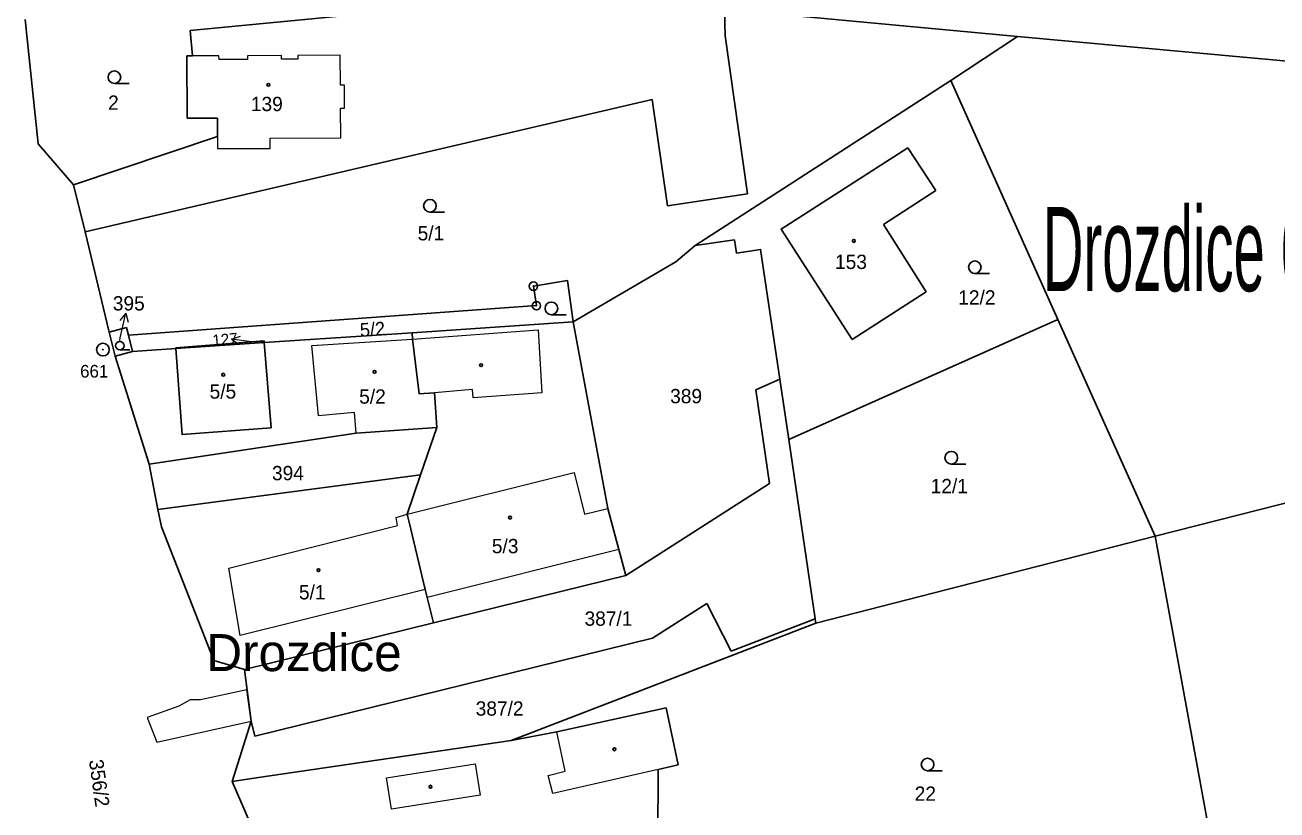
# Model space of a CAD drawing. Extents: x -645290 to -643454, y -1064771 to -1062356.
# Drawn here: x -644572.2 to -644423.3, y -1063667.6 to -1063574.3 of the extents above; entities that cross this region are included whole.
import ezdxf
from ezdxf.enums import TextEntityAlignment as Align

# ---------------------------------------------------------------- set-up
doc = ezdxf.new("R2010")
doc.units = 0
doc.header["$LTSCALE"] = 0.68
for name, color, linetype, lineweight in [('1', 7, 'Continuous', 25), ('13', 7, 'Continuous', 13), ('3', 7, 'Continuous', 25), ('4', 7, 'Continuous', 13), ('5', 7, 'Continuous', 25), ('7', 7, 'Continuous', 13), ('8', 7, 'Continuous', 25)]:
    doc.layers.add(name, color=color, linetype=linetype, lineweight=lineweight)
doc.layers.add('2', color=7, linetype='Continuous')

msp = doc.modelspace()

# ---------------------------------------------------------------- linework, layer by layer
at = {"layer": '1'}
for p, q in [((-644552.52, -1063574.93), (-644514.96, -1063571.32)), ((-644488.95, -1063575.57), (-644489.03, -1063572.44)), ((-644480.96, -1063573.16), (-644454.17, -1063575.65)), ((-644572.16, -1063573.65), (-644570.58, -1063588.42)), ((-644552.26, -1063577.97), (-644552.52, -1063574.93)), ((-644454.17, -1063575.65), (-644462.11, -1063580.89)), ((-644403.42, -1063580.33), (-644454.17, -1063575.65)), ((-644552.91, -1063577.97), (-644552.89, -1063585.38)), ((-644552.26, -1063577.97), (-644552.91, -1063577.97)), ((-644462.11, -1063580.89), (-644492.51, -1063600.51)), ((-644462.11, -1063580.89), (-644449.39, -1063609.28)), ((-644565, -1063598.89), (-644497.63, -1063583.14)), ((-644497.63, -1063583.14), (-644495.79, -1063595.78)), ((-644552.89, -1063585.38), (-644549.27, -1063585.38)), ((-644549.27, -1063585.38), (-644549.27, -1063587.55)), ((-644566.4, -1063593.27), (-644549.27, -1063587.55)), ((-644570.58, -1063588.42), (-644566.4, -1063593.27)), ((-644467.24, -1063588.87), (-644463.91, -1063593.96)), ((-644566.4, -1063593.27), (-644565, -1063598.89)), ((-644463.91, -1063593.96), (-644470.13, -1063598)), ((-644470.13, -1063598), (-644465.06, -1063606.02)), ((-644565, -1063598.89), (-644562.17, -1063610.79)), ((-644492.51, -1063600.51), (-644487.83, -1063599.81)), ((-644487.83, -1063599.81), (-644487.59, -1063601.41)), ((-644494.79, -1063602.46), (-644492.51, -1063600.51)), ((-644506.99, -1063609.57), (-644494.79, -1063602.46)), ((-644507.67, -1063604.66), (-644511.73, -1063605.33)), ((-644507.67, -1063604.66), (-644506.99, -1063609.57)), ((-644511.73, -1063605.33), (-644511.38, -1063607.65)), ((-644465.06, -1063606.02), (-644473.86, -1063611.67)), ((-644511.38, -1063607.65), (-644559.87, -1063611.17)), ((-644562.17, -1063610.79), (-644560.11, -1063610.25)), ((-644560.11, -1063610.25), (-644559.87, -1063611.17)), ((-644526.15, -1063610.87), (-644506.99, -1063609.57)), ((-644502.88, -1063631.75), (-644506.99, -1063609.57)), ((-644481.39, -1063623.58), (-644449.39, -1063609.28)), ((-644449.39, -1063609.28), (-644437.84, -1063635.07)), ((-644562.17, -1063610.79), (-644561.45, -1063613.64)), ((-644559.87, -1063611.17), (-644559.37, -1063613.11)), ((-644526.15, -1063610.87), (-644526.11, -1063611.65)), ((-644526.11, -1063611.65), (-644525.3, -1063618.15)), ((-644561.45, -1063613.64), (-644559.37, -1063613.11)), ((-644561.45, -1063613.64), (-644557.4, -1063626.48)), ((-644485.3, -1063617.66), (-644482.45, -1063616.39)), ((-644482.45, -1063616.39), (-644481.39, -1063623.58)), ((-644525.3, -1063618.15), (-644523.49, -1063618.03)), ((-644523.49, -1063618.03), (-644523.22, -1063622.12)), ((-644483.65, -1063628.81), (-644485.3, -1063617.66)), ((-644532.79, -1063622.8), (-644523.22, -1063622.12)), ((-644523.22, -1063622.12), (-644525.15, -1063627.78)), ((-644557.4, -1063626.48), (-644537.04, -1063623.43)), ((-644537.04, -1063623.43), (-644532.79, -1063622.8)), ((-644481.39, -1063623.58), (-644478.25, -1063644.88)), ((-644557.4, -1063626.48), (-644556.37, -1063631.89)), ((-644556.37, -1063631.89), (-644525.15, -1063627.78)), ((-644525.15, -1063627.78), (-644526.74, -1063632.43)), ((-644500.76, -1063639.72), (-644483.65, -1063628.81)), ((-644420.53, -1063630.64), (-644437.84, -1063635.07)), ((-644556.37, -1063631.89), (-644555.92, -1063633.94)), ((-644526.74, -1063632.43), (-644526.49, -1063633.41)), ((-644502.88, -1063631.75), (-644501.58, -1063636.64)), ((-644555.92, -1063633.94), (-644549.72, -1063649.83)), ((-644526.49, -1063633.41), (-644524.6, -1063641.4)), ((-644478.17, -1063645.39), (-644437.84, -1063635.07)), ((-644437.84, -1063635.07), (-644429.45, -1063680.78)), ((-644501.58, -1063636.64), (-644500.76, -1063639.72)), ((-644523.6, -1063645.36), (-644500.76, -1063639.72)), ((-644524.6, -1063641.4), (-644524.37, -1063642.33)), ((-644524.37, -1063642.33), (-644523.6, -1063645.36)), ((-644497.57, -1063647.18), (-644491.13, -1063643.07)), ((-644491.13, -1063643.07), (-644488.23, -1063648.73)), ((-644488.23, -1063648.73), (-644478.25, -1063644.88)), ((-644478.25, -1063644.88), (-644478.17, -1063645.39)), ((-644546.09, -1063650.91), (-644523.6, -1063645.36)), ((-644514.39, -1063659.34), (-644478.17, -1063645.39)), ((-644544.85, -1063658.85), (-644497.57, -1063647.18)), ((-644549.72, -1063649.83), (-644546.09, -1063650.91)), ((-644546.09, -1063650.91), (-644545.29, -1063657.03)), ((-644508.96, -1063658.32), (-644495.97, -1063655.45)), ((-644495.97, -1063655.45), (-644494.53, -1063662.24)), ((-644545.29, -1063657.03), (-644547.55, -1063664.21)), ((-644545.29, -1063657.03), (-644544.85, -1063658.85)), ((-644544.4, -1063663.73), (-644514.39, -1063659.34)), ((-644514.39, -1063659.34), (-644508.96, -1063658.32)), ((-644494.53, -1063662.24), (-644496.92, -1063662.78)), ((-644547.55, -1063664.21), (-644544.4, -1063663.73)), ((-644547.55, -1063664.21), (-644542.97, -1063674.78)), ((-644496.92, -1063662.78), (-644496.93, -1063678.61))]:
    msp.add_line(p, q, dxfattribs=at)
for points in [[(-644495.79, -1063595.78), (-644486.29, -1063594.35), (-644488.95, -1063575.57)], [(-644473.86, -1063611.67), (-644482.3, -1063598.55), (-644467.24, -1063588.87)], [(-644487.59, -1063601.41), (-644484.73, -1063600.97), (-644482.45, -1063616.39)], [(-644559.37, -1063613.11), (-644554.23, -1063612.76), (-644543.72, -1063612.05)], [(-644543.72, -1063612.05), (-644543.74, -1063611.84), (-644554.24, -1063612.67), (-644554.23, -1063612.76)], [(-644554.23, -1063612.76), (-644553.5, -1063622.98), (-644542.92, -1063622.17), (-644543.72, -1063612.05), (-644526.15, -1063610.87)]]:
    msp.add_lwpolyline(points, dxfattribs=at)
at = {"layer": '13'}
msp.add_lwpolyline([(-644545.29, -1063657.03), (-644545.78, -1063653.31), (-644551.32, -1063654.51), (-644552.53, -1063654.52), (-644553.88, -1063655.28), (-644557.63, -1063656.63), (-644556.51, -1063659.55)], close=True, dxfattribs=at)
at = {"layer": '3'}
for p, q in [((-644561.543, -1063581.24), (-644559.793, -1063581.24)), ((-644524.033, -1063596.53), (-644522.283, -1063596.53)), ((-644459.263, -1063603.83), (-644457.513, -1063603.83)), ((-644509.593, -1063608.73), (-644507.843, -1063608.73)), ((-644560.885, -1063612.91), (-644559.713, -1063612.91)), ((-644462.063, -1063626.48), (-644460.313, -1063626.48)), ((-644464.883, -1063662.95), (-644463.133, -1063662.95))]:
    msp.add_line(p, q, dxfattribs=at)
for centre, radius in [((-644561.5429, -1063580.4898), 0.75), ((-644524.0329, -1063595.7798), 0.75), ((-644459.2629, -1063603.0798), 0.75), ((-644509.5929, -1063607.9798), 0.75), ((-644560.8852, -1063612.4074), 0.5025), ((-644462.0629, -1063625.7298), 0.75), ((-644464.8829, -1063662.1998), 0.75)]:
    msp.add_circle(centre, radius, dxfattribs=at)
at = {"layer": '4'}
for p, q in [((-644541.69, -1063577.91), (-644545.72, -1063577.94)), ((-644541.69, -1063578.34), (-644541.69, -1063577.91)), ((-644534.69, -1063577.88), (-644539.72, -1063577.91)), ((-644539.72, -1063577.91), (-644539.72, -1063578.33)), ((-644534.68, -1063581.42), (-644534.69, -1063577.88)), ((-644549.11, -1063577.96), (-644552.26, -1063577.97)), ((-644549.09, -1063578.39), (-644549.11, -1063577.96)), ((-644545.72, -1063578.37), (-644549.09, -1063578.39)), ((-644545.72, -1063577.94), (-644545.72, -1063578.37)), ((-644539.72, -1063578.33), (-644541.69, -1063578.34)), ((-644534.18, -1063581.43), (-644534.68, -1063581.42)), ((-644534.17, -1063584.18), (-644534.18, -1063581.43)), ((-644534.67, -1063584.18), (-644534.17, -1063584.18)), ((-644534.62, -1063587.71), (-644534.67, -1063584.18)), ((-644549.27, -1063587.55), (-644549.27, -1063588.95)), ((-644543.04, -1063587.75), (-644534.62, -1063587.71)), ((-644543.03, -1063588.95), (-644543.04, -1063587.75)), ((-644549.27, -1063588.95), (-644543.03, -1063588.95)), ((-644526.11, -1063611.65), (-644511.17, -1063610.53)), ((-644511.17, -1063610.53), (-644510.72, -1063618.03)), ((-644538.05, -1063612.4), (-644526.11, -1063611.65)), ((-644537.29, -1063620.75), (-644538.05, -1063612.4)), ((-644518.96, -1063617.62), (-644523.49, -1063618.03)), ((-644518.89, -1063618.62), (-644518.96, -1063617.62)), ((-644510.72, -1063618.03), (-644518.89, -1063618.62)), ((-644532.99, -1063620.37), (-644537.29, -1063620.75)), ((-644532.79, -1063622.8), (-644532.99, -1063620.37)), ((-644526.74, -1063632.43), (-644506.9, -1063627.47)), ((-644506.9, -1063627.47), (-644505.65, -1063632.45)), ((-644528.04, -1063632.82), (-644526.74, -1063632.43)), ((-644527.88, -1063633.79), (-644528.04, -1063632.82)), ((-644505.65, -1063632.45), (-644502.88, -1063631.75)), ((-644547.92, -1063638.84), (-644527.88, -1063633.79)), ((-644501.58, -1063636.64), (-644524.37, -1063642.33)), ((-644546.57, -1063646.87), (-644547.92, -1063638.84)), ((-644524.6, -1063641.4), (-644546.57, -1063646.87)), ((-644507.94, -1063662.98), (-644508.96, -1063658.32)), ((-644529.2, -1063663.79), (-644518.64, -1063662.12)), ((-644518.64, -1063662.12), (-644518.06, -1063665.84)), ((-644528.61, -1063667.5), (-644529.2, -1063663.79)), ((-644509.98, -1063663.51), (-644507.94, -1063662.98)), ((-644509.43, -1063665.65), (-644509.98, -1063663.51)), ((-644496.92, -1063662.78), (-644509.43, -1063665.65)), ((-644518.06, -1063665.84), (-644528.61, -1063667.5))]:
    msp.add_line(p, q, dxfattribs=at)
at = {"layer": '5'}
for centre, radius in [((-644543.2268, -1063581.3992), 0.175), ((-644473.6468, -1063599.9492), 0.175), ((-644543.9946, -1063611.9594), 0.1172), ((-644517.9468, -1063614.7292), 0.175), ((-644548.5968, -1063615.8692), 0.175), ((-644530.6068, -1063615.5192), 0.175), ((-644514.5068, -1063632.8492), 0.175), ((-644537.2768, -1063639.0992), 0.175), ((-644502.1068, -1063660.3892), 0.175), ((-644523.9668, -1063664.8492), 0.175)]:
    msp.add_circle(centre, radius, dxfattribs=at)
at = {"layer": '7'}
for p, q in [((-644560.165, -1063608.536), (-644560.878, -1063609.399)), ((-644547.609, -1063611.654), (-644546.676, -1063612.273))]:
    msp.add_line(p, q, dxfattribs=at)
for points in [[(-644560.91, -1063611.78), (-644560.84, -1063611.46), (-644560.165, -1063608.536), (-644559.902, -1063609.624)], [(-644544.46, -1063612.04), (-644544.63, -1063612.02), (-644547.609, -1063611.654), (-644546.554, -1063611.279)]]:
    msp.add_lwpolyline(points, dxfattribs=at)
at = {"layer": '8'}
for centre, radius in [((-644511.73, -1063605.3299), 0.5), ((-644511.73, -1063605.3299), 0.0303), ((-644511.38, -1063607.6499), 0.5), ((-644511.38, -1063607.6499), 0.0303), ((-644562.9, -1063612.8698), 0.75), ((-644562.9, -1063612.8698), 0.03)]:
    msp.add_circle(centre, radius, dxfattribs=at)

# ---------------------------------------------------------------- texts
at = {"layer": '2'}
for s, p in [('2', (-644561.65, -1063584.365)), ('139', (-644543.419, -1063584.525)), ('5/1', (-644523.91, -1063599.885)), ('12/2', (-644459.019, -1063607.525)), ('395', (-644559.829, -1063608.225)), ('5/5', (-644548.64, -1063618.705)), ('5/2', (-644530.86, -1063619.304)), ('389', (-644493.579, -1063619.255)), ('394', (-644540.909, -1063628.405)), ('12/1', (-644462.299, -1063629.945)), ('5/3', (-644515.09, -1063637.084)), ('5/1', (-644538.02, -1063642.574)), ('387/1', (-644502.81, -1063645.705)), ('387/2', (-644515.75, -1063656.395)), ('22', (-644465.149, -1063666.515))]:
    msp.add_text(s, height=1.7, dxfattribs=at).set_placement(p, align=Align.CENTER)
msp.add_text('153', height=1.7, dxfattribs=at).set_placement((-644475.88, -1063603.295))
for s, height, rotation, p in [('5/2', 1.617, 4, (-644530.8024, -1063611.2605)), ('127', 1.353, 5, (-644548.3295, -1063612.3442)), ('356/2', 1.7, 278, (-644564.1718, -1063664.5287))]:
    msp.add_text(s, height=height, rotation=rotation, dxfattribs=at).set_placement(p, align=Align.CENTER)
at = {"layer": '7', "width": 0.5}
msp.add_text('Drozdice 619973', height=10, dxfattribs=at).set_placement((-644425.9, -1063605.923), align=Align.CENTER)
at = {"layer": '7'}
msp.add_text('Drozdice', height=4.4, dxfattribs=at).set_placement((-644538.999, -1063651.1), align=Align.CENTER)
at = {"layer": '8'}
msp.add_text('661', height=1.5, dxfattribs=at).set_placement((-644565.61, -1063616.195))

doc.saveas('drawing.dxf')
